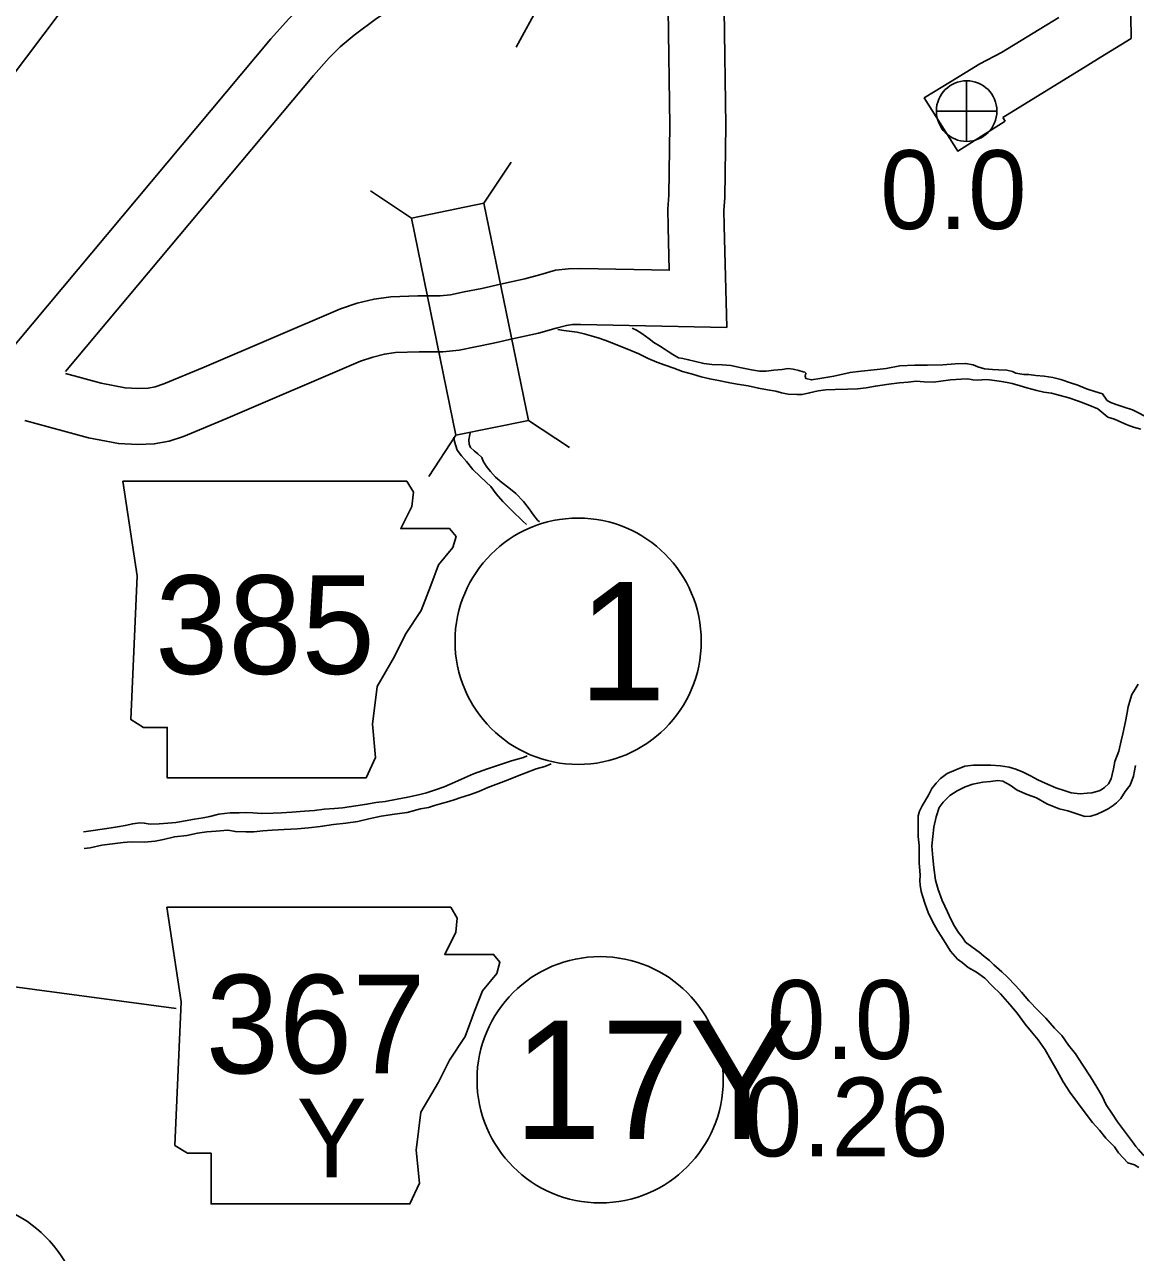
# Model space of a CAD drawing. Extents: x -939622 to -934222, y 1383701 to 1385301.
# Drawn here: x -936303.09 to -936285.22, y 1384541.55 to 1384561.29 of the extents above; entities that cross this region are included whole.
import ezdxf

# ---------------------------------------------------------------- set-up
doc = ezdxf.new("R2010")
doc.units = 0
for name, color, linetype in [('10', 7, 'Continuous'), ('15', 7, 'Continuous'), ('20', 7, 'Continuous'), ('21', 7, 'Continuous'), ('22', 7, 'Continuous'), ('25', 7, 'Continuous'), ('26', 7, 'Continuous'), ('27', 7, 'Continuous'), ('9', 7, 'Continuous')]:
    doc.layers.add(name, color=color, linetype=linetype)

msp = doc.modelspace()

# ---------------------------------------------------------------- linework, layer by layer
at = {"layer": '10'}
for points in [[(-936303.43, 1384555.913), (-936299.125, 1384561.055), (-936298.844, 1384561.373), (-936298.614, 1384561.598), (-936298.347, 1384561.821), (-936297.945, 1384562.12), (-936295.363, 1384563.81), (-936294.955, 1384564.07), (-936294.664, 1384564.249), (-936294.325, 1384564.415), (-936293.976, 1384564.528), (-936293.168, 1384564.767), (-936292.786, 1384564.829), (-936292.461, 1384564.875), (-936292.072, 1384564.904), (-936291.422, 1384564.919), (-936290.867, 1384564.912), (-936290.662, 1384564.922), (-936290.381, 1384564.94), (-936290.092, 1384564.987), (-936289.846, 1384565.045), (-936289.538, 1384565.157), (-936289.278, 1384565.281), (-936286.29, 1384566.816)], [(-936285.385, 1384566.291), (-936285.341, 1384564.418), (-936285.293, 1384561.06)], [(-936302.428, 1384555.707), (-936298.442, 1384560.468), (-936298.191, 1384560.753), (-936298.01, 1384560.93), (-936297.789, 1384561.115), (-936297.43, 1384561.382), (-936294.874, 1384563.054), (-936294.477, 1384563.307), (-936294.229, 1384563.46), (-936293.987, 1384563.578), (-936293.71, 1384563.668), (-936292.968, 1384563.887), (-936292.65, 1384563.939), (-936292.364, 1384563.979), (-936292.028, 1384564.004), (-936291.417, 1384564.019), (-936290.849, 1384564.012), (-936290.61, 1384564.024), (-936290.28, 1384564.045), (-936289.917, 1384564.104), (-936289.589, 1384564.181), (-936289.189, 1384564.326), (-936288.878, 1384564.475), (-936286.262, 1384565.818)], [(-936291.862, 1384563.383), (-936291.812, 1384559.666), (-936291.826, 1384558.503), (-936291.842, 1384558.294), (-936291.836, 1384558.051), (-936291.796, 1384556.417), (-936294.146, 1384556.465), (-936294.274, 1384556.462), (-936294.374, 1384556.45), (-936294.541, 1384556.403), (-936294.825, 1384556.324), (-936295.24, 1384556.233), (-936295.547, 1384556.165), (-936295.834, 1384556.106), (-936296.099, 1384556.05), (-936296.36, 1384556.026), (-936296.743, 1384556.023), (-936297.123, 1384556.011), (-936297.299, 1384555.988), (-936297.489, 1384555.941), (-936297.683, 1384555.875), (-936299.848, 1384554.947), (-936300.531, 1384554.665), (-936300.762, 1384554.588), (-936301.002, 1384554.545), (-936301.267, 1384554.535), (-936301.578, 1384554.549), (-936302.061, 1384554.644), (-936303.084, 1384554.918)], [(-936292.763, 1384563.4), (-936292.712, 1384559.665), (-936292.726, 1384558.541), (-936292.742, 1384558.316), (-936292.735, 1384558.029), (-936292.719, 1384557.336), (-936294.148, 1384557.365), (-936294.339, 1384557.361), (-936294.55, 1384557.335), (-936294.783, 1384557.27), (-936295.042, 1384557.198), (-936295.433, 1384557.112), (-936295.735, 1384557.045), (-936296.017, 1384556.988), (-936296.235, 1384556.942), (-936296.406, 1384556.926), (-936296.761, 1384556.923), (-936297.197, 1384556.909), (-936297.465, 1384556.873), (-936297.74, 1384556.806), (-936298.005, 1384556.716), (-936300.197, 1384555.776), (-936300.846, 1384555.509), (-936300.985, 1384555.462), (-936301.098, 1384555.442), (-936301.264, 1384555.436), (-936301.47, 1384555.445), (-936301.857, 1384555.522), (-936302.429, 1384555.674)], [(-936286.458, 1384561.4), (-936287.378, 1384560.835), (-936287.728, 1384560.653), (-936288.197, 1384560.366)], [(-936285.293, 1384561.06), (-936285.79, 1384560.754), (-936285.987, 1384560.633)], [(-936285.987, 1384560.633), (-936287.358, 1384559.791)], [(-936288.197, 1384560.366), (-936288.621, 1384560.107), (-936288.082, 1384559.252), (-936287.32, 1384559.732)], [(-936287.32, 1384559.732), (-936287.358, 1384559.791)]]:
    msp.add_lwpolyline(points, dxfattribs=at)
at = {"layer": '15'}
msp.add_lwpolyline([(-936306.205, 1384556.586), (-936300.78, 1384563.789)], dxfattribs=at)
at = {"layer": '20'}
for p, q in [((-936294.801, 1384561.619), (-936295.179, 1384560.923)), ((-936295.7, 1384558.412), (-936295.264, 1384559.073)), ((-936296.864, 1384558.174), (-936297.525, 1384558.611)), ((-936294.986, 1384554.92), (-936294.325, 1384554.484)), ((-936296.15, 1384554.682), (-936296.587, 1384554.021))]:
    msp.add_line(p, q, dxfattribs=at)
msp.add_lwpolyline([(-936294.986, 1384554.92), (-936295.7, 1384558.412), (-936296.864, 1384558.174), (-936296.15, 1384554.682)], close=True, dxfattribs=at)
at = {"layer": '21'}
for points in [[(-936301.504, 1384553.945), (-936301.276, 1384552.423), (-936301.377, 1384550.113), (-936301.174, 1384549.986), (-936300.793, 1384549.986), (-936300.793, 1384549.174), (-936297.596, 1384549.174), (-936297.444, 1384549.504), (-936297.494, 1384550.037), (-936297.418, 1384550.646), (-936297.139, 1384551.128), (-936296.961, 1384551.484), (-936296.708, 1384551.864), (-936296.555, 1384552.27), (-936296.429, 1384552.6), (-936296.2, 1384552.879), (-936296.149, 1384553.057), (-936296.251, 1384553.184), (-936297.038, 1384553.184), (-936296.86, 1384553.539), (-936296.835, 1384553.767), (-936296.94, 1384553.943)], [(-936300.797, 1384547.098), (-936300.569, 1384545.575), (-936300.671, 1384543.266), (-936300.468, 1384543.139), (-936300.087, 1384543.139), (-936300.087, 1384542.327), (-936296.889, 1384542.327), (-936296.737, 1384542.657), (-936296.788, 1384543.19), (-936296.712, 1384543.799), (-936296.433, 1384544.281), (-936296.255, 1384544.637), (-936296.001, 1384545.017), (-936295.849, 1384545.423), (-936295.722, 1384545.753), (-936295.494, 1384546.032), (-936295.443, 1384546.21), (-936295.544, 1384546.337), (-936296.331, 1384546.337), (-936296.154, 1384546.692), (-936296.128, 1384546.92), (-936296.233, 1384547.096)]]:
    msp.add_lwpolyline(points, close=True, dxfattribs=at)
msp.add_lwpolyline([(-936310.582, 1384546.721), (-936310.171, 1384547.863), (-936306.61, 1384546.264), (-936300.651, 1384545.465)], dxfattribs=at)
at = {"layer": '26'}
for p, q in [((-936287.938, 1384559.407), (-936287.938, 1384560.382)), ((-936288.425, 1384559.895), (-936287.45, 1384559.895))]:
    msp.add_line(p, q, dxfattribs=at)
msp.add_circle((-936287.938, 1384559.895), 0.487, dxfattribs=at)
at = {"layer": '27'}
for centre in [(-936294.185, 1384551.371), (-936293.831, 1384544.322), (-936304.149, 1384540.399)]:
    msp.add_circle(centre, 1.98, dxfattribs=at)
at = {"layer": '9'}
for points in [[(-936293.316, 1384556.405), (-936293.248, 1384556.371), (-936293.163, 1384556.319), (-936293.044, 1384556.232), (-936292.967, 1384556.174), (-936292.876, 1384556.122), (-936292.803, 1384556.072), (-936292.739, 1384556.032), (-936292.662, 1384555.979), (-936292.574, 1384555.93), (-936292.502, 1384555.917), (-936292.408, 1384555.898), (-936292.317, 1384555.873), (-936292.163, 1384555.838), (-936292.034, 1384555.82), (-936291.868, 1384555.815), (-936291.73, 1384555.803), (-936291.561, 1384555.768), (-936291.398, 1384555.736), (-936291.268, 1384555.712), (-936291.16, 1384555.715), (-936291.038, 1384555.727), (-936290.903, 1384555.742), (-936290.807, 1384555.754), (-936290.726, 1384555.744), (-936290.635, 1384555.725), (-936290.569, 1384555.705), (-936290.541, 1384555.697), (-936290.526, 1384555.679), (-936290.523, 1384555.67), (-936290.528, 1384555.658), (-936290.537, 1384555.634), (-936290.524, 1384555.598), (-936290.433, 1384555.573), (-936290.299, 1384555.595), (-936290.074, 1384555.633), (-936289.812, 1384555.694), (-936289.635, 1384555.716), (-936289.425, 1384555.736), (-936289.231, 1384555.759), (-936289.012, 1384555.8), (-936288.772, 1384555.809), (-936288.565, 1384555.811), (-936288.319, 1384555.817), (-936288.121, 1384555.834), (-936287.956, 1384555.838), (-936287.832, 1384555.814), (-936287.757, 1384555.783), (-936287.651, 1384555.749), (-936287.524, 1384555.74), (-936287.428, 1384555.736), (-936287.293, 1384555.728), (-936287.199, 1384555.706), (-936287.145, 1384555.683), (-936287.021, 1384555.662), (-936286.937, 1384555.661), (-936286.825, 1384555.643), (-936286.693, 1384555.634), (-936286.551, 1384555.61), (-936286.424, 1384555.577), (-936286.27, 1384555.527), (-936286.152, 1384555.488), (-936286.009, 1384555.431), (-936285.876, 1384555.389), (-936285.755, 1384555.347), (-936285.683, 1384555.247)], [(-936285.67, 1384554.976), (-936285.827, 1384555.107), (-936285.982, 1384555.17), (-936286.137, 1384555.229), (-936286.294, 1384555.286), (-936286.491, 1384555.341), (-936286.575, 1384555.36), (-936286.696, 1384555.375), (-936286.811, 1384555.405), (-936286.968, 1384555.447), (-936287.077, 1384555.48), (-936287.204, 1384555.513), (-936287.288, 1384555.532), (-936287.379, 1384555.548), (-936287.49, 1384555.563), (-936287.614, 1384555.578), (-936287.692, 1384555.574), (-936287.76, 1384555.569), (-936287.839, 1384555.576), (-936287.917, 1384555.589), (-936288.028, 1384555.583), (-936288.199, 1384555.576), (-936288.352, 1384555.551), (-936288.471, 1384555.537), (-936288.619, 1384555.542), (-936288.748, 1384555.551), (-936288.877, 1384555.539), (-936289.018, 1384555.526), (-936289.191, 1384555.504), (-936289.404, 1384555.475), (-936289.556, 1384555.447), (-936289.694, 1384555.429), (-936289.856, 1384555.422), (-936290.054, 1384555.42), (-936290.201, 1384555.413), (-936290.327, 1384555.395), (-936290.464, 1384555.365), (-936290.581, 1384555.341), (-936290.668, 1384555.339), (-936290.809, 1384555.344), (-936290.915, 1384555.363), (-936291.008, 1384555.391), (-936291.138, 1384555.412), (-936291.286, 1384555.438), (-936291.452, 1384555.476), (-936291.627, 1384555.502), (-936291.772, 1384555.532), (-936291.928, 1384555.561), (-936292.07, 1384555.588), (-936292.209, 1384555.623), (-936292.345, 1384555.665), (-936292.506, 1384555.709), (-936292.648, 1384555.76), (-936292.784, 1384555.811), (-936292.921, 1384555.859), (-936293.057, 1384555.916), (-936293.209, 1384555.993), (-936293.337, 1384556.047), (-936293.458, 1384556.095), (-936293.579, 1384556.144), (-936293.697, 1384556.189), (-936293.849, 1384556.242), (-936293.973, 1384556.282), (-936294.088, 1384556.312), (-936294.202, 1384556.339), (-936294.413, 1384556.37), (-936294.514, 1384556.383)], [(-936284.43, 1384554.807), (-936284.557, 1384554.816), (-936284.704, 1384554.83), (-936284.843, 1384554.869), (-936284.941, 1384554.914), (-936285.045, 1384554.972), (-936285.151, 1384555.032), (-936285.273, 1384555.092), (-936285.406, 1384555.134), (-936285.503, 1384555.167), (-936285.61, 1384555.207), (-936285.661, 1384555.229), (-936285.683, 1384555.247)], [(-936285.67, 1384554.976), (-936285.558, 1384554.94), (-936285.445, 1384554.889), (-936285.357, 1384554.849), (-936285.257, 1384554.813), (-936285.139, 1384554.783)], [(-936295.016, 1384553.25), (-936295.072, 1384553.304), (-936295.253, 1384553.471), (-936295.398, 1384553.618), (-936295.503, 1384553.744), (-936295.59, 1384553.857), (-936295.664, 1384553.93), (-936295.759, 1384554.018), (-936295.879, 1384554.135), (-936295.978, 1384554.259), (-936296.058, 1384554.351), (-936296.13, 1384554.445), (-936296.172, 1384554.583), (-936296.183, 1384554.653)], [(-936295.918, 1384554.738), (-936295.925, 1384554.694), (-936295.944, 1384554.609), (-936295.94, 1384554.54), (-936295.914, 1384554.484), (-936295.856, 1384554.431), (-936295.798, 1384554.387), (-936295.736, 1384554.328), (-936295.711, 1384554.266), (-936295.661, 1384554.18), (-936295.596, 1384554.103), (-936295.513, 1384554.009), (-936295.411, 1384553.924), (-936295.298, 1384553.837), (-936295.188, 1384553.746)], [(-936295.188, 1384553.746), (-936295.065, 1384553.617), (-936294.975, 1384553.502), (-936294.897, 1384553.392), (-936294.838, 1384553.318), (-936294.806, 1384553.291)], [(-936285.178, 1384550.68), (-936285.23, 1384550.603), (-936285.282, 1384550.518), (-936285.304, 1384550.448), (-936285.343, 1384550.318), (-936285.364, 1384550.194)], [(-936285.364, 1384550.194), (-936285.382, 1384550.079), (-936285.428, 1384549.885), (-936285.455, 1384549.77), (-936285.493, 1384549.603)], [(-936298.956, 1384548.613), (-936298.788, 1384548.623), (-936298.587, 1384548.64), (-936298.425, 1384548.652), (-936298.27, 1384548.671), (-936298.102, 1384548.684), (-936297.976, 1384548.696), (-936297.76, 1384548.726), (-936297.581, 1384548.751), (-936297.44, 1384548.779), (-936297.288, 1384548.797), (-936297.093, 1384548.835), (-936296.926, 1384548.866), (-936296.753, 1384548.904), (-936296.621, 1384548.937), (-936296.481, 1384548.982), (-936296.338, 1384549.031), (-936296.169, 1384549.107), (-936296.011, 1384549.177), (-936295.866, 1384549.238), (-936295.64, 1384549.322), (-936295.467, 1384549.38), (-936295.258, 1384549.448), (-936295.064, 1384549.504), (-936295.005, 1384549.528)], [(-936285.493, 1384549.603), (-936285.555, 1384549.44), (-936285.577, 1384549.322), (-936285.598, 1384549.231), (-936285.612, 1384549.159), (-936285.655, 1384549.077), (-936285.72, 1384549.021), (-936285.776, 1384548.983), (-936285.808, 1384548.968), (-936285.925, 1384548.935), (-936286, 1384548.927), (-936286.114, 1384548.921), (-936286.255, 1384548.933), (-936286.37, 1384548.972), (-936286.503, 1384549.017), (-936286.673, 1384549.088), (-936286.792, 1384549.145), (-936286.91, 1384549.209), (-936287.029, 1384549.266), (-936287.147, 1384549.317), (-936287.256, 1384549.348), (-936287.395, 1384549.371), (-936287.551, 1384549.38), (-936287.689, 1384549.382), (-936287.83, 1384549.379), (-936287.968, 1384549.363), (-936288.111, 1384549.303), (-936288.25, 1384549.245), (-936288.357, 1384549.167), (-936288.43, 1384549.09), (-936288.5, 1384549.002), (-936288.554, 1384548.895), (-936288.652, 1384548.727), (-936288.695, 1384548.642), (-936288.72, 1384548.563), (-936288.718, 1384548.461), (-936288.718, 1384548.352), (-936288.715, 1384548.232), (-936288.703, 1384548.088), (-936288.699, 1384547.908), (-936288.702, 1384547.802), (-936288.69, 1384547.688), (-936288.685, 1384547.604), (-936288.689, 1384547.526), (-936288.685, 1384547.448), (-936288.67, 1384547.349), (-936288.644, 1384547.262), (-936288.609, 1384547.161), (-936288.551, 1384546.997), (-936288.462, 1384546.818), (-936288.409, 1384546.72), (-936288.349, 1384546.629), (-936288.281, 1384546.531)], [(-936294.62, 1384549.403), (-936294.719, 1384549.359), (-936294.862, 1384549.32), (-936295.025, 1384549.258), (-936295.165, 1384549.204), (-936295.311, 1384549.143), (-936295.466, 1384549.082), (-936295.638, 1384549.021), (-936295.784, 1384548.957), (-936295.915, 1384548.906), (-936296.088, 1384548.854), (-936296.162, 1384548.828), (-936296.267, 1384548.795), (-936296.38, 1384548.765), (-936296.496, 1384548.729), (-936296.592, 1384548.7), (-936296.72, 1384548.679), (-936296.935, 1384548.619), (-936297.136, 1384548.594), (-936297.354, 1384548.558), (-936297.551, 1384548.514), (-936297.727, 1384548.474), (-936297.919, 1384548.448), (-936298.119, 1384548.425), (-936298.332, 1384548.396), (-936298.521, 1384548.37), (-936298.697, 1384548.354), (-936298.91, 1384548.343), (-936299.105, 1384548.335), (-936299.255, 1384548.322), (-936299.399, 1384548.31), (-936299.531, 1384548.31), (-936299.696, 1384548.312), (-936299.82, 1384548.333), (-936300.006, 1384548.319), (-936300.156, 1384548.307), (-936300.308, 1384548.285), (-936300.479, 1384548.251), (-936300.676, 1384548.225), (-936300.855, 1384548.187), (-936300.984, 1384548.16), (-936301.164, 1384548.141), (-936301.371, 1384548.145), (-936301.5, 1384548.136), (-936301.67, 1384548.116), (-936301.844, 1384548.091), (-936302.032, 1384548.051), (-936302.128, 1384548.039)], [(-936285.461, 1384548.843), (-936285.389, 1384548.956), (-936285.31, 1384549.058), (-936285.254, 1384549.204), (-936285.222, 1384549.373)], [(-936287.957, 1384546.533), (-936288.007, 1384546.607), (-936288.069, 1384546.689), (-936288.134, 1384546.793), (-936288.194, 1384546.903), (-936288.248, 1384547.022), (-936288.333, 1384547.201), (-936288.398, 1384547.379), (-936288.437, 1384547.532), (-936288.466, 1384547.733), (-936288.482, 1384547.889), (-936288.496, 1384548.084), (-936288.484, 1384548.232), (-936288.467, 1384548.383), (-936288.429, 1384548.549), (-936288.378, 1384548.698), (-936288.314, 1384548.786), (-936288.206, 1384548.894), (-936288.088, 1384548.969), (-936287.963, 1384549.033), (-936287.838, 1384549.075), (-936287.68, 1384549.106), (-936287.557, 1384549.115), (-936287.434, 1384549.133), (-936287.356, 1384549.123), (-936287.24, 1384549.056), (-936287.127, 1384548.978), (-936286.963, 1384548.909), (-936286.815, 1384548.853), (-936286.647, 1384548.758), (-936286.453, 1384548.675), (-936286.311, 1384548.645), (-936286.184, 1384548.603), (-936286.039, 1384548.556), (-936285.943, 1384548.558), (-936285.838, 1384548.594), (-936285.746, 1384548.635), (-936285.663, 1384548.679), (-936285.58, 1384548.729), (-936285.527, 1384548.776), (-936285.461, 1384548.843)], [(-936302.141, 1384548.305), (-936302.096, 1384548.311), (-936301.766, 1384548.361), (-936301.593, 1384548.389), (-936301.47, 1384548.41), (-936301.348, 1384548.437), (-936301.231, 1384548.452), (-936301.162, 1384548.448), (-936301.066, 1384548.432), (-936300.924, 1384548.435), (-936300.784, 1384548.445), (-936300.655, 1384548.457), (-936300.502, 1384548.485), (-936300.356, 1384548.509), (-936300.215, 1384548.531), (-936300.108, 1384548.555), (-936299.961, 1384548.591), (-936299.782, 1384548.611), (-936299.637, 1384548.614), (-936299.526, 1384548.617), (-936299.415, 1384548.613), (-936299.277, 1384548.605), (-936299.091, 1384548.609), (-936298.956, 1384548.613)], [(-936285.254, 1384543.301), (-936285.515, 1384543.644), (-936285.605, 1384543.783), (-936285.693, 1384543.92), (-936285.759, 1384544.06), (-936285.844, 1384544.202), (-936285.947, 1384544.368), (-936286.071, 1384544.555), (-936286.19, 1384544.738), (-936286.298, 1384544.88), (-936286.41, 1384545.031), (-936286.524, 1384545.151), (-936286.666, 1384545.31), (-936286.789, 1384545.434), (-936286.94, 1384545.59), (-936287.054, 1384545.728), (-936287.147, 1384545.834), (-936287.286, 1384545.976), (-936287.374, 1384546.055), (-936287.5, 1384546.169), (-936287.571, 1384546.239), (-936287.666, 1384546.315), (-936287.739, 1384546.371), (-936287.834, 1384546.441), (-936287.957, 1384546.533)], [(-936288.281, 1384546.531), (-936288.196, 1384546.387), (-936288.085, 1384546.263), (-936288.012, 1384546.205), (-936287.911, 1384546.129), (-936287.78, 1384546.054), (-936287.645, 1384545.955), (-936287.525, 1384545.834), (-936287.393, 1384545.705), (-936287.245, 1384545.531), (-936287.124, 1384545.39), (-936286.997, 1384545.215), (-936286.895, 1384545.094), (-936286.79, 1384544.965), (-936286.678, 1384544.805), (-936286.587, 1384544.644), (-936286.48, 1384544.467), (-936286.386, 1384544.288), (-936286.277, 1384544.125), (-936286.153, 1384543.957), (-936286.047, 1384543.812), (-936285.917, 1384543.635), (-936285.803, 1384543.511), (-936285.701, 1384543.381), (-936285.559, 1384543.243), (-936285.497, 1384543.148), (-936285.423, 1384543.066), (-936285.346, 1384542.986), (-936285.239, 1384542.953)], [(-936282.51, 1384542.29), (-936282.713, 1384542.35), (-936282.905, 1384542.417), (-936283.116, 1384542.456), (-936283.307, 1384542.505), (-936283.53, 1384542.541), (-936283.696, 1384542.581), (-936283.862, 1384542.612), (-936284.046, 1384542.646), (-936284.201, 1384542.69), (-936284.398, 1384542.76), (-936284.544, 1384542.822), (-936284.653, 1384542.861), (-936284.817, 1384542.929), (-936284.937, 1384543), (-936285.025, 1384543.055), (-936285.105, 1384543.122), (-936285.176, 1384543.198), (-936285.217, 1384543.248), (-936285.254, 1384543.301)], [(-936285.171, 1384542.912), (-936285.239, 1384542.953)]]:
    msp.add_lwpolyline(points, dxfattribs=at)

# ---------------------------------------------------------------- texts
at = {"layer": '21'}
for s, p in [('385', (-936300.988, 1384550.847)), ('367', (-936300.173, 1384544.426))]:
    msp.add_text(s, height=1.584, dxfattribs=at).set_placement(p)
at = {"layer": '22'}
msp.add_text('Y', height=1.267, dxfattribs=at).set_placement((-936298.713, 1384542.753))
at = {"layer": '25'}
for s, p in [('0.0', (-936289.329, 1384557.998)), ('0.0', (-936291.15, 1384544.656)), ('0.26', (-936291.524, 1384543.09))]:
    msp.add_text(s, height=1.2672, dxfattribs=at).set_placement(p)
at = {"layer": '27'}
for s, height, p in [('1', 1.901, (-936294.185, 1384550.421)), ('17Y', 1.9008, (-936295.225, 1384543.371))]:
    msp.add_text(s, height=height, dxfattribs=at).set_placement(p)

doc.saveas('drawing.dxf')
